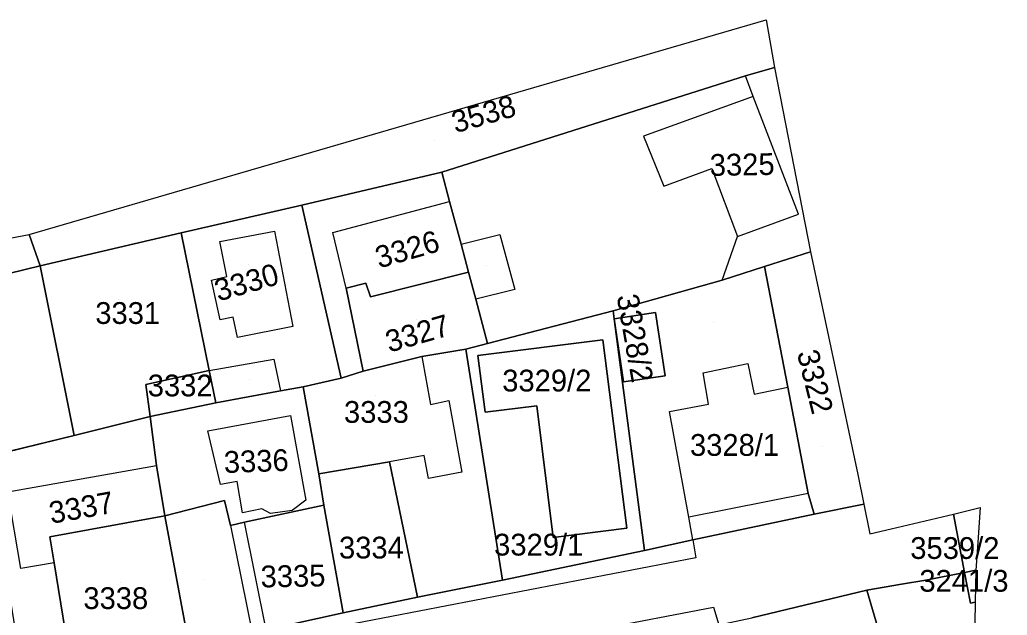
# Model space of a CAD drawing. Extents: x -262657 to -261595, y -1238015 to -1237156.
# Drawn here: x -261893.4 to -261802.8, y -1237693.7 to -1237639 of the extents above; entities that cross this region are included whole.
import ezdxf

# ---------------------------------------------------------------- set-up
doc = ezdxf.new("R2010")
doc.units = 0
for name, color, linetype in [('body_kn', 7, 'Continuous'), ('kladpar_druhypozemkov', 7, 'Continuous'), ('kladpar_hranice', 7, 'Continuous'), ('kladpar_parcelnecisla', 7, 'Continuous'), ('kladpar_plochy', 7, 'Continuous'), ('zappar_hrandruhpozemk', 7, 'Continuous')]:
    doc.layers.add(name, color=color, linetype=linetype)

msp = doc.modelspace()

# ---------------------------------------------------------------- linework, layer by layer
at = {"layer": 'body_kn'}
for p, q in [((-261824.9, -1237639.02), (-261824.9, -1237639.02)), ((-261824.15, -1237643.4), (-261824.15, -1237643.4)), ((-261826.8, -1237644.16), (-261826.8, -1237644.16)), ((-261826.08, -1237646.08), (-261826.08, -1237646.08)), ((-261836.17, -1237649.71), (-261836.17, -1237649.71)), ((-261854.67, -1237653), (-261854.67, -1237653)), ((-261829.89, -1237652.67), (-261829.89, -1237652.67)), ((-261834.3, -1237654.29), (-261834.3, -1237654.29)), ((-261867.52, -1237656.05), (-261867.52, -1237656.05)), ((-261867.52, -1237656.05), (-261867.52, -1237656.05)), ((-261853.95, -1237655.71), (-261853.95, -1237655.71)), ((-261821.94, -1237656.88), (-261821.94, -1237656.88)), ((-261892.53, -1237658.72), (-261892.53, -1237658.72)), ((-261878.59, -1237658.58), (-261878.59, -1237658.58)), ((-261878.59, -1237658.58), (-261878.59, -1237658.58)), ((-261870, -1237658.44), (-261870, -1237658.44)), ((-261870, -1237658.44), (-261870, -1237658.44)), ((-261864.65, -1237658.56), (-261864.65, -1237658.56)), ((-261849.33, -1237658.74), (-261849.33, -1237658.74)), ((-261875.03, -1237659.38), (-261875.03, -1237659.38)), ((-261852.9, -1237659.61), (-261852.9, -1237659.61)), ((-261852.9, -1237659.61), (-261852.9, -1237659.61)), ((-261827.53, -1237658.93), (-261827.53, -1237658.93)), ((-261827.53, -1237658.93), (-261827.53, -1237658.93)), ((-261820.82, -1237660.31), (-261820.82, -1237660.31)), ((-261820.82, -1237660.31), (-261820.82, -1237660.31)), ((-261891.53, -1237661.6), (-261891.53, -1237661.6)), ((-261891.53, -1237661.6), (-261891.53, -1237661.6)), ((-261852.21, -1237662.18), (-261852.21, -1237662.18)), ((-261825.06, -1237661.67), (-261825.06, -1237661.67)), ((-261875.79, -1237662.91), (-261875.79, -1237662.91)), ((-261874.38, -1237662.58), (-261874.38, -1237662.58)), ((-261861.62, -1237663.19), (-261861.62, -1237663.19)), ((-261828.95, -1237662.91), (-261828.95, -1237662.91)), ((-261828.95, -1237662.91), (-261828.95, -1237662.91)), ((-261863.43, -1237663.65), (-261863.43, -1237663.65)), ((-261863.43, -1237663.65), (-261863.43, -1237663.65)), ((-261847.96, -1237663.78), (-261847.96, -1237663.78)), ((-261861.22, -1237664.46), (-261861.22, -1237664.46)), ((-261851.55, -1237664.67), (-261851.55, -1237664.67)), ((-261838.94, -1237665.73), (-261838.94, -1237665.73)), ((-261838.94, -1237665.73), (-261838.94, -1237665.73)), ((-261835.05, -1237665.9), (-261835.05, -1237665.9)), ((-261875, -1237666.57), (-261875, -1237666.57)), ((-261873.8, -1237666.31), (-261873.8, -1237666.31)), ((-261838.86, -1237666.47), (-261838.86, -1237666.47)), ((-261838.86, -1237666.47), (-261838.86, -1237666.47)), ((-261868.33, -1237667.18), (-261868.33, -1237667.18)), ((-261873.4, -1237668.18), (-261873.4, -1237668.18)), ((-261850.46, -1237668.73), (-261850.46, -1237668.73)), ((-261839.88, -1237668.4), (-261839.88, -1237668.4)), ((-261852.47, -1237669.26), (-261852.47, -1237669.26)), ((-261852.47, -1237669.26), (-261852.47, -1237669.26)), ((-261870.07, -1237670.16), (-261870.07, -1237670.16)), ((-261856.51, -1237669.93), (-261856.51, -1237669.93)), ((-261856.51, -1237669.93), (-261856.51, -1237669.93)), ((-261851.35, -1237669.84), (-261851.35, -1237669.84)), ((-261851.35, -1237669.84), (-261851.35, -1237669.84)), ((-261826.57, -1237670.56), (-261826.57, -1237670.56)), ((-261876.02, -1237671.22), (-261876.02, -1237671.22)), ((-261876.02, -1237671.22), (-261876.02, -1237671.22)), ((-261861.87, -1237671.27), (-261861.87, -1237671.27)), ((-261830.68, -1237671.43), (-261830.68, -1237671.43)), ((-261863.91, -1237671.91), (-261863.91, -1237671.91)), ((-261837.98, -1237672.27), (-261837.98, -1237672.27)), ((-261834.18, -1237671.7), (-261834.18, -1237671.7)), ((-261881.81, -1237672.51), (-261881.81, -1237672.51)), ((-261869.46, -1237673.07), (-261869.46, -1237673.07)), ((-261867.37, -1237672.72), (-261867.37, -1237672.72)), ((-261822.9, -1237672.74), (-261822.9, -1237672.74)), ((-261875.39, -1237674.19), (-261875.39, -1237674.19)), ((-261854.02, -1237673.98), (-261854.02, -1237673.98)), ((-261825.99, -1237673.4), (-261825.99, -1237673.4)), ((-261855.7, -1237674.33), (-261855.7, -1237674.33)), ((-261850.69, -1237675.05), (-261850.69, -1237675.05)), ((-261845.95, -1237674.45), (-261845.95, -1237674.45)), ((-261833.78, -1237674.98), (-261833.78, -1237674.98)), ((-261830.18, -1237674.29), (-261830.18, -1237674.29)), ((-261881.43, -1237675.43), (-261881.43, -1237675.43)), ((-261881.43, -1237675.43), (-261881.43, -1237675.43)), ((-261868.54, -1237675.34), (-261868.54, -1237675.34)), ((-261868.54, -1237675.34), (-261868.54, -1237675.34)), ((-261876.13, -1237676.75), (-261876.13, -1237676.75)), ((-261888.4, -1237677.17), (-261888.4, -1237677.17)), ((-261859.47, -1237679.61), (-261859.47, -1237679.61)), ((-261856.29, -1237679.03), (-261856.29, -1237679.03)), ((-261880.83, -1237679.94), (-261880.83, -1237679.94)), ((-261852.84, -1237680.55), (-261852.84, -1237680.55)), ((-261873.45, -1237681.4), (-261873.45, -1237681.4)), ((-261865.94, -1237680.7), (-261865.94, -1237680.7)), ((-261855.88, -1237681.14), (-261855.88, -1237681.14)), ((-261816.5, -1237680.75), (-261816.5, -1237680.75)), ((-261874.98, -1237681.69), (-261874.98, -1237681.69)), ((-261874.6, -1237683.14), (-261874.6, -1237683.14)), ((-261867.14, -1237683.12), (-261867.14, -1237683.12)), ((-261821.04, -1237682.49), (-261821.04, -1237682.49)), ((-261821.04, -1237682.49), (-261821.04, -1237682.49)), ((-261871.19, -1237683.92), (-261871.19, -1237683.92)), ((-261868.38, -1237684.05), (-261868.38, -1237684.05)), ((-261865.48, -1237683.57), (-261865.48, -1237683.57)), ((-261815.95, -1237683.47), (-261815.95, -1237683.47)), ((-261805.25, -1237683.8), (-261805.25, -1237683.8)), ((-261880.07, -1237684.56), (-261880.07, -1237684.56)), ((-261880.07, -1237684.56), (-261880.07, -1237684.56)), ((-261872.94, -1237684.27), (-261872.94, -1237684.27)), ((-261870.39, -1237684.33), (-261870.39, -1237684.33)), ((-261832, -1237684.67), (-261832, -1237684.67)), ((-261820.51, -1237684.41), (-261820.51, -1237684.41)), ((-261807.71, -1237684.39), (-261807.71, -1237684.39)), ((-261807.71, -1237684.39), (-261807.71, -1237684.39)), ((-261874.06, -1237685.43), (-261874.06, -1237685.43)), ((-261874.06, -1237685.43), (-261874.06, -1237685.43)), ((-261872.78, -1237685.14), (-261872.78, -1237685.14)), ((-261837.68, -1237685.68), (-261837.68, -1237685.68)), ((-261813.42, -1237685.74), (-261813.42, -1237685.74)), ((-261890.62, -1237686.47), (-261890.62, -1237686.47)), ((-261844.43, -1237686.53), (-261844.43, -1237686.53)), ((-261831.64, -1237686.76), (-261831.64, -1237686.76)), ((-261831.64, -1237686.76), (-261831.64, -1237686.76)), ((-261815.39, -1237686.21), (-261815.39, -1237686.21)), ((-261836.05, -1237687.73), (-261836.05, -1237687.73)), ((-261805.49, -1237687.01), (-261805.49, -1237687.01)), ((-261831.35, -1237688.4), (-261831.35, -1237688.4)), ((-261893.29, -1237689.39), (-261893.29, -1237689.39)), ((-261890.23, -1237688.87), (-261890.23, -1237688.87)), ((-261890.23, -1237688.87), (-261890.23, -1237688.87)), ((-261805.66, -1237689.55), (-261805.66, -1237689.55)), ((-261849.08, -1237690.46), (-261849.08, -1237690.46)), ((-261849.08, -1237690.46), (-261849.08, -1237690.46)), ((-261810.26, -1237690.45), (-261810.26, -1237690.45)), ((-261806.69, -1237689.75), (-261806.69, -1237689.75)), ((-261806.69, -1237689.75), (-261806.69, -1237689.75)), ((-261815.65, -1237691.39), (-261815.65, -1237691.39)), ((-261812.47, -1237690.82), (-261812.47, -1237690.82)), ((-261856.9, -1237692.02), (-261856.9, -1237692.02)), ((-261856.9, -1237692.02), (-261856.9, -1237692.02)), ((-261829.72, -1237692.94), (-261829.72, -1237692.94)), ((-261806.16, -1237692.56), (-261806.16, -1237692.56)), ((-261805.71, -1237692.47), (-261805.71, -1237692.47)), ((-261863.71, -1237693.45), (-261863.71, -1237693.45))]:
    msp.add_line(p, q, dxfattribs=at)
at = {"layer": 'kladpar_druhypozemkov'}
for p, q in [((-261855.36, -1237650.09), (-261855.36, -1237650.09)), ((-261827.39, -1237651.5), (-261827.39, -1237651.5)), ((-261858.05, -1237658.61), (-261858.05, -1237658.61)), ((-261872.41, -1237661.46), (-261872.41, -1237661.46)), ((-261850.54, -1237661.59), (-261850.54, -1237661.59)), ((-261884.31, -1237664.7), (-261884.31, -1237664.7)), ((-261857.03, -1237666.56), (-261857.03, -1237666.56)), ((-261829.72, -1237666.79), (-261829.72, -1237666.79)), ((-261835.86, -1237668.66), (-261835.86, -1237668.66)), ((-261843.89, -1237671.21), (-261843.89, -1237671.21)), ((-261877.07, -1237672.07), (-261877.07, -1237672.07)), ((-261872.28, -1237672.07), (-261872.28, -1237672.07)), ((-261860.77, -1237673.49), (-261860.77, -1237673.49)), ((-261827.26, -1237676.99), (-261827.26, -1237676.99)), ((-261871.29, -1237678.38), (-261871.29, -1237678.38)), ((-261819.75, -1237678.15), (-261819.75, -1237678.15)), ((-261887.49, -1237682.91), (-261887.49, -1237682.91)), ((-261826.6, -1237685.22), (-261826.6, -1237685.22)), ((-261846.39, -1237686.39), (-261846.39, -1237686.39)), ((-261861.11, -1237687.07), (-261861.11, -1237687.07)), ((-261806.37, -1237687.29), (-261806.37, -1237687.29)), ((-261868.13, -1237688.99), (-261868.13, -1237688.99)), ((-261876.5, -1237690.42), (-261876.5, -1237690.42)), ((-261806.11, -1237690.24), (-261806.11, -1237690.24)), ((-261884.18, -1237690.7), (-261884.18, -1237690.7))]:
    msp.add_line(p, q, dxfattribs=at)
at = {"layer": 'kladpar_hranice'}
for points in [[(-261891.53, -1237661.6), (-261892.53, -1237658.72), (-261824.9, -1237639.02), (-261824.15, -1237643.4), (-261826.8, -1237644.16), (-261854.67, -1237653), (-261867.52, -1237656.05), (-261878.59, -1237658.58), (-261891.53, -1237661.6)], [(-261820.82, -1237660.31), (-261825.06, -1237661.67), (-261828.95, -1237662.91), (-261838.94, -1237665.73), (-261850.46, -1237668.73), (-261851.55, -1237664.67), (-261852.21, -1237662.18), (-261852.9, -1237659.61), (-261853.95, -1237655.71), (-261854.67, -1237653), (-261826.8, -1237644.16), (-261824.15, -1237643.4), (-261820.82, -1237660.31)], [(-261867.52, -1237656.05), (-261854.67, -1237653), (-261853.95, -1237655.71), (-261852.9, -1237659.61), (-261852.21, -1237662.18), (-261861.22, -1237664.46), (-261861.62, -1237663.19), (-261863.43, -1237663.65), (-261861.87, -1237671.27), (-261863.91, -1237671.91), (-261867.52, -1237656.05)], [(-261878.59, -1237658.58), (-261867.52, -1237656.05), (-261863.91, -1237671.91), (-261867.37, -1237672.72), (-261869.46, -1237673.07), (-261875.39, -1237674.19), (-261876.02, -1237671.22), (-261878.59, -1237658.58)], [(-261942.23, -1237673.66), (-261942.75, -1237671.05), (-261918.88, -1237665.11), (-261918.59, -1237665.04), (-261895.61, -1237659.32), (-261892.53, -1237658.72), (-261891.53, -1237661.6), (-261924.29, -1237669.63), (-261942.23, -1237673.66)], [(-261891.53, -1237661.6), (-261878.59, -1237658.58), (-261876.02, -1237671.22), (-261881.81, -1237672.51), (-261881.43, -1237675.43), (-261888.4, -1237677.17), (-261891.53, -1237661.6)], [(-261821.04, -1237682.49), (-261822.9, -1237672.74), (-261825.06, -1237661.67), (-261820.82, -1237660.31), (-261816.5, -1237680.75), (-261815.95, -1237683.47), (-261820.51, -1237684.41), (-261821.04, -1237682.49)], [(-261921, -1237684.46), (-261923.17, -1237673.65), (-261924.29, -1237669.63), (-261891.53, -1237661.6), (-261888.4, -1237677.17), (-261896.29, -1237679.1), (-261900.65, -1237679.95), (-261904.39, -1237680.71), (-261907.95, -1237681.68), (-261912.12, -1237682.58), (-261921, -1237684.46)], [(-261852.47, -1237669.26), (-261856.51, -1237669.93), (-261861.87, -1237671.27), (-261863.43, -1237663.65), (-261861.62, -1237663.19), (-261861.22, -1237664.46), (-261852.21, -1237662.18), (-261851.55, -1237664.67), (-261850.46, -1237668.73), (-261852.47, -1237669.26)], [(-261838.94, -1237665.73), (-261828.95, -1237662.91), (-261825.06, -1237661.67), (-261822.9, -1237672.74), (-261821.04, -1237682.49), (-261820.51, -1237684.41), (-261831.64, -1237686.76), (-261836.05, -1237687.73), (-261838.86, -1237666.47), (-261837.98, -1237672.27), (-261834.18, -1237671.7), (-261835.05, -1237665.9), (-261838.86, -1237666.47), (-261838.94, -1237665.73)], [(-261838.94, -1237665.73), (-261838.86, -1237666.47), (-261836.05, -1237687.73), (-261849.08, -1237690.46), (-261852.47, -1237669.26), (-261850.46, -1237668.73), (-261838.94, -1237665.73)], [(-261838.86, -1237666.47), (-261835.05, -1237665.9), (-261834.18, -1237671.7), (-261837.98, -1237672.27), (-261838.86, -1237666.47)], [(-261851.35, -1237669.84), (-261839.88, -1237668.4), (-261837.68, -1237685.68), (-261844.43, -1237686.53), (-261845.95, -1237674.45), (-261850.69, -1237675.05), (-261851.35, -1237669.84)], [(-261839.88, -1237668.4), (-261851.35, -1237669.84), (-261850.69, -1237675.05), (-261845.95, -1237674.45), (-261844.43, -1237686.53), (-261837.68, -1237685.68), (-261839.88, -1237668.4)], [(-261849.08, -1237690.46), (-261856.9, -1237692.02), (-261859.47, -1237679.61), (-261865.94, -1237680.7), (-261867.37, -1237672.72), (-261863.91, -1237671.91), (-261861.87, -1237671.27), (-261856.51, -1237669.93), (-261852.47, -1237669.26), (-261849.08, -1237690.46)], [(-261881.43, -1237675.43), (-261881.81, -1237672.51), (-261876.02, -1237671.22), (-261875.39, -1237674.19), (-261881.43, -1237675.43)], [(-261880.07, -1237684.56), (-261880.83, -1237679.94), (-261881.43, -1237675.43), (-261875.39, -1237674.19), (-261869.46, -1237673.07), (-261867.37, -1237672.72), (-261865.94, -1237680.7), (-261865.48, -1237683.57), (-261872.78, -1237685.14), (-261874.06, -1237685.43), (-261874.6, -1237683.14), (-261880.07, -1237684.56)], [(-261888.62, -1237698.85), (-261893.08, -1237699.52), (-261894.9, -1237687.92), (-261895.29, -1237685.45), (-261896.29, -1237679.1), (-261888.4, -1237677.17), (-261881.43, -1237675.43), (-261880.83, -1237679.94), (-261880.07, -1237684.56), (-261890.62, -1237686.47), (-261890.23, -1237688.87), (-261888.62, -1237698.85)], [(-261856.9, -1237692.02), (-261863.71, -1237693.45), (-261865.48, -1237683.57), (-261865.94, -1237680.7), (-261859.47, -1237679.61), (-261856.9, -1237692.02)], [(-261877.74, -1237697), (-261880.07, -1237684.56), (-261874.6, -1237683.14), (-261874.06, -1237685.43), (-261872.78, -1237685.14), (-261865.48, -1237683.57), (-261863.71, -1237693.45), (-261870.79, -1237695.02), (-261872.02, -1237695.41), (-261877.74, -1237697)], [(-261870.79, -1237695.02), (-261863.71, -1237693.45), (-261856.9, -1237692.02), (-261849.08, -1237690.46), (-261836.05, -1237687.73), (-261831.64, -1237686.76), (-261820.51, -1237684.41), (-261815.95, -1237683.47), (-261815.39, -1237686.21), (-261813.42, -1237685.74), (-261807.71, -1237684.39), (-261806.69, -1237689.75), (-261810.26, -1237690.45), (-261812.47, -1237690.82), (-261815.65, -1237691.39), (-261826.22, -1237693.91)], [(-261807.71, -1237684.39), (-261805.25, -1237683.8), (-261805.49, -1237687.01), (-261805.66, -1237689.55), (-261806.69, -1237689.75), (-261807.71, -1237684.39)], [(-261877.74, -1237697), (-261888.62, -1237698.85), (-261890.23, -1237688.87), (-261890.62, -1237686.47), (-261880.07, -1237684.56), (-261877.74, -1237697)], [(-261806.69, -1237689.75), (-261805.66, -1237689.55), (-261805.71, -1237692.47), (-261806.16, -1237692.56), (-261806.69, -1237689.75)], [(-261806.69, -1237689.75), (-261806.16, -1237692.56), (-261805.71, -1237692.47), (-261805.84, -1237700.16), (-261806, -1237709.55), (-261806.16, -1237717.33), (-261810.54, -1237718.01), (-261812.29, -1237702.86), (-261815.65, -1237691.39), (-261812.47, -1237690.82), (-261810.26, -1237690.45), (-261806.69, -1237689.75)], [(-261829.24, -1237694.55), (-261826.22, -1237693.91), (-261815.65, -1237691.39), (-261812.29, -1237702.86), (-261810.54, -1237718.01), (-261810.39, -1237722.04), (-261821.2, -1237723.42), (-261824.29, -1237723.84), (-261824.85, -1237720.78), (-261827, -1237707.23), (-261828.65, -1237697.67), (-261829.24, -1237694.55)]]:
    msp.add_lwpolyline(points, dxfattribs=at)
at = {"layer": 'kladpar_plochy'}
for p, q in [((-261924.29, -1237669.63), (-261891.53, -1237661.6)), ((-261891.53, -1237661.6), (-261888.4, -1237677.17)), ((-261850.46, -1237668.73), (-261838.94, -1237665.73)), ((-261838.94, -1237665.73), (-261838.86, -1237666.47)), ((-261838.86, -1237666.47), (-261836.05, -1237687.73)), ((-261852.47, -1237669.26), (-261850.46, -1237668.73)), ((-261839.88, -1237668.4), (-261851.35, -1237669.84)), ((-261837.68, -1237685.68), (-261839.88, -1237668.4)), ((-261849.08, -1237690.46), (-261852.47, -1237669.26)), ((-261851.35, -1237669.84), (-261850.69, -1237675.05)), ((-261850.69, -1237675.05), (-261845.95, -1237674.45)), ((-261845.95, -1237674.45), (-261844.43, -1237686.53)), ((-261888.4, -1237677.17), (-261896.29, -1237679.1)), ((-261844.43, -1237686.53), (-261837.68, -1237685.68)), ((-261836.05, -1237687.73), (-261849.08, -1237690.46))]:
    msp.add_line(p, q, dxfattribs=at)
for points in [[(-261891.53, -1237661.6), (-261892.53, -1237658.72), (-261824.9, -1237639.02), (-261824.15, -1237643.4), (-261826.8, -1237644.16), (-261854.67, -1237653), (-261867.52, -1237656.05), (-261878.59, -1237658.58)], [(-261820.82, -1237660.31), (-261825.06, -1237661.67), (-261828.95, -1237662.91), (-261838.94, -1237665.73), (-261850.46, -1237668.73), (-261851.55, -1237664.67), (-261852.21, -1237662.18), (-261852.9, -1237659.61), (-261853.95, -1237655.71), (-261854.67, -1237653), (-261826.8, -1237644.16), (-261824.15, -1237643.4)], [(-261867.52, -1237656.05), (-261854.67, -1237653), (-261853.95, -1237655.71), (-261852.9, -1237659.61), (-261852.21, -1237662.18), (-261861.22, -1237664.46), (-261861.62, -1237663.19), (-261863.43, -1237663.65), (-261861.87, -1237671.27), (-261863.91, -1237671.91)], [(-261878.59, -1237658.58), (-261867.52, -1237656.05), (-261863.91, -1237671.91), (-261867.37, -1237672.72), (-261869.46, -1237673.07), (-261875.39, -1237674.19), (-261876.02, -1237671.22)], [(-261942.23, -1237673.66), (-261942.75, -1237671.05), (-261918.88, -1237665.11), (-261918.59, -1237665.04), (-261895.61, -1237659.32), (-261892.53, -1237658.72), (-261891.53, -1237661.6), (-261924.29, -1237669.63)], [(-261891.53, -1237661.6), (-261878.59, -1237658.58), (-261876.02, -1237671.22), (-261881.81, -1237672.51), (-261881.43, -1237675.43), (-261888.4, -1237677.17)], [(-261821.04, -1237682.49), (-261822.9, -1237672.74), (-261825.06, -1237661.67), (-261820.82, -1237660.31), (-261816.5, -1237680.75), (-261815.95, -1237683.47), (-261820.51, -1237684.41)], [(-261852.47, -1237669.26), (-261856.51, -1237669.93), (-261861.87, -1237671.27), (-261863.43, -1237663.65), (-261861.62, -1237663.19), (-261861.22, -1237664.46), (-261852.21, -1237662.18), (-261851.55, -1237664.67), (-261850.46, -1237668.73)], [(-261838.94, -1237665.73), (-261828.95, -1237662.91), (-261825.06, -1237661.67), (-261822.9, -1237672.74), (-261821.04, -1237682.49), (-261820.51, -1237684.41), (-261831.64, -1237686.76), (-261836.05, -1237687.73), (-261838.86, -1237666.47), (-261837.98, -1237672.27), (-261834.18, -1237671.7), (-261835.05, -1237665.9), (-261838.86, -1237666.47)], [(-261838.86, -1237666.47), (-261835.05, -1237665.9), (-261834.18, -1237671.7), (-261837.98, -1237672.27)], [(-261851.35, -1237669.84), (-261839.88, -1237668.4), (-261837.68, -1237685.68), (-261844.43, -1237686.53), (-261845.95, -1237674.45), (-261850.69, -1237675.05)], [(-261849.08, -1237690.46), (-261856.9, -1237692.02), (-261859.47, -1237679.61), (-261865.94, -1237680.7), (-261867.37, -1237672.72), (-261863.91, -1237671.91), (-261861.87, -1237671.27), (-261856.51, -1237669.93), (-261852.47, -1237669.26)], [(-261881.43, -1237675.43), (-261881.81, -1237672.51), (-261876.02, -1237671.22), (-261875.39, -1237674.19)], [(-261880.07, -1237684.56), (-261880.83, -1237679.94), (-261881.43, -1237675.43), (-261875.39, -1237674.19), (-261869.46, -1237673.07), (-261867.37, -1237672.72), (-261865.94, -1237680.7), (-261865.48, -1237683.57), (-261872.78, -1237685.14), (-261874.06, -1237685.43), (-261874.6, -1237683.14)], [(-261888.62, -1237698.85), (-261893.08, -1237699.52), (-261894.9, -1237687.92), (-261895.29, -1237685.45), (-261896.29, -1237679.1), (-261888.4, -1237677.17), (-261881.43, -1237675.43), (-261880.83, -1237679.94), (-261880.07, -1237684.56), (-261890.62, -1237686.47), (-261890.23, -1237688.87)], [(-261856.9, -1237692.02), (-261863.71, -1237693.45), (-261865.48, -1237683.57), (-261865.94, -1237680.7), (-261859.47, -1237679.61)], [(-261877.74, -1237697), (-261880.07, -1237684.56), (-261874.6, -1237683.14), (-261874.06, -1237685.43), (-261872.78, -1237685.14), (-261865.48, -1237683.57), (-261863.71, -1237693.45), (-261870.79, -1237695.02), (-261872.02, -1237695.41)], [(-261807.71, -1237684.39), (-261805.25, -1237683.8), (-261805.49, -1237687.01), (-261805.66, -1237689.55), (-261806.69, -1237689.75)], [(-261877.74, -1237697), (-261888.62, -1237698.85), (-261890.23, -1237688.87), (-261890.62, -1237686.47), (-261880.07, -1237684.56)], [(-261806.69, -1237689.75), (-261805.66, -1237689.55), (-261805.71, -1237692.47), (-261806.16, -1237692.56)], [(-261806.69, -1237689.75), (-261806.16, -1237692.56), (-261805.71, -1237692.47), (-261805.84, -1237700.16), (-261806, -1237709.55), (-261806.16, -1237717.33), (-261810.54, -1237718.01), (-261812.29, -1237702.86), (-261815.65, -1237691.39), (-261812.47, -1237690.82), (-261810.26, -1237690.45)], [(-261829.24, -1237694.55), (-261826.22, -1237693.91), (-261815.65, -1237691.39), (-261812.29, -1237702.86), (-261810.54, -1237718.01), (-261810.39, -1237722.04), (-261821.2, -1237723.42), (-261824.29, -1237723.84), (-261824.85, -1237720.78), (-261827, -1237707.23), (-261828.65, -1237697.67)]]:
    msp.add_lwpolyline(points, close=True, dxfattribs=at)
msp.add_lwpolyline([(-261870.79, -1237695.02), (-261863.71, -1237693.45), (-261856.9, -1237692.02), (-261849.08, -1237690.46), (-261836.05, -1237687.73), (-261831.64, -1237686.76), (-261820.51, -1237684.41), (-261815.95, -1237683.47), (-261815.39, -1237686.21), (-261813.42, -1237685.74), (-261807.71, -1237684.39), (-261806.69, -1237689.75), (-261810.26, -1237690.45), (-261812.47, -1237690.82), (-261815.65, -1237691.39), (-261826.22, -1237693.91)], dxfattribs=at)
at = {"layer": 'zappar_hrandruhpozemk'}
for p, q in [((-261826.08, -1237646.08), (-261826.8, -1237644.16)), ((-261826.08, -1237646.08), (-261836.17, -1237649.71)), ((-261821.94, -1237656.88), (-261826.08, -1237646.08)), ((-261836.17, -1237649.71), (-261834.3, -1237654.29)), ((-261864.65, -1237658.56), (-261853.95, -1237655.71)), ((-261827.53, -1237658.93), (-261821.94, -1237656.88)), ((-261875.03, -1237659.38), (-261870, -1237658.44)), ((-261863.43, -1237663.65), (-261864.65, -1237658.56)), ((-261852.9, -1237659.61), (-261849.33, -1237658.74)), ((-261849.33, -1237658.74), (-261847.96, -1237663.78)), ((-261828.95, -1237662.91), (-261827.53, -1237658.93)), ((-261847.96, -1237663.78), (-261851.55, -1237664.67)), ((-261876.02, -1237671.22), (-261870.07, -1237670.16)), ((-261870.07, -1237670.16), (-261869.46, -1237673.07)), ((-261830.68, -1237671.43), (-261826.57, -1237670.56)), ((-261854.02, -1237673.98), (-261852.84, -1237680.55)), ((-261876.13, -1237676.75), (-261868.54, -1237675.34)), ((-261894.48, -1237682.36), (-261880.83, -1237679.94)), ((-261821.04, -1237682.49), (-261832, -1237684.67)), ((-261874.06, -1237685.43), (-261872.02, -1237695.41)), ((-261870.79, -1237695.02), (-261872.78, -1237685.14)), ((-261831.64, -1237686.76), (-261831.35, -1237688.4)), ((-261831.35, -1237688.4), (-261870.9, -1237696.02))]:
    msp.add_line(p, q, dxfattribs=at)
for points in [[(-261834.3, -1237654.29), (-261829.89, -1237652.67), (-261827.53, -1237658.93)], [(-261870, -1237658.44), (-261868.33, -1237667.18), (-261873.4, -1237668.18), (-261873.8, -1237666.31), (-261875, -1237666.57), (-261875.79, -1237662.91), (-261874.38, -1237662.58), (-261875.03, -1237659.38)], [(-261856.51, -1237669.93), (-261855.7, -1237674.33), (-261854.02, -1237673.98)], [(-261826.57, -1237670.56), (-261825.99, -1237673.4), (-261822.9, -1237672.74)], [(-261831.64, -1237686.76), (-261832, -1237684.67), (-261833.78, -1237674.98), (-261830.18, -1237674.29), (-261830.68, -1237671.43)], [(-261868.54, -1237675.34), (-261867.14, -1237683.12), (-261868.38, -1237684.05), (-261870.39, -1237684.33), (-261871.19, -1237683.92), (-261872.94, -1237684.27), (-261873.45, -1237681.4), (-261874.98, -1237681.69), (-261876.13, -1237676.75)], [(-261852.84, -1237680.55), (-261855.88, -1237681.14), (-261856.29, -1237679.03), (-261859.47, -1237679.61)], [(-261890.23, -1237688.87), (-261893.29, -1237689.39), (-261894.48, -1237682.36)], [(-261869.66, -1237700.6), (-261840.58, -1237695.01), (-261829.72, -1237692.94), (-261829.24, -1237694.55)]]:
    msp.add_lwpolyline(points, dxfattribs=at)

# ---------------------------------------------------------------- texts
at = {"layer": 'kladpar_parcelnecisla'}
for s, rotation, p in [('3538', 16, (-261853.416, -1237649.447)), ('3325', 1, (-261830.059, -1237653.36)), ('3326', 16, (-261860.424, -1237661.859)), ('3330', 16, (-261875.169, -1237664.892)), ('3328/2', 280, (-261838.628, -1237664.384)), ('3327', 16, (-261859.489, -1237669.586)), ('3322', 284, (-261822.094, -1237669.587)), ('3336', 2, (-261874.63, -1237680.629)), ('3337', 10, (-261890.505, -1237685.29)), ('3335', 1, (-261871.274, -1237691.13))]:
    msp.add_text(s, height=2, rotation=rotation, dxfattribs=at).set_placement(p)
for s, p in [('3331', (-261886.458, -1237666.94)), ('3329/2', (-261849.118, -1237673.14)), ('3332', (-261881.644, -1237673.59)), ('3333', (-261863.64, -1237676.02)), ('3328/1', (-261831.893, -1237679.05)), ('3334', (-261864.097, -1237688.47)), ('3329/1', (-261849.862, -1237688.2)), ('3539/2', (-261811.677, -1237688.51)), ('3241/3', (-261810.842, -1237691.52)), ('3338', (-261887.551, -1237693.11))]:
    msp.add_text(s, height=2, dxfattribs=at).set_placement(p)

doc.saveas('drawing.dxf')
